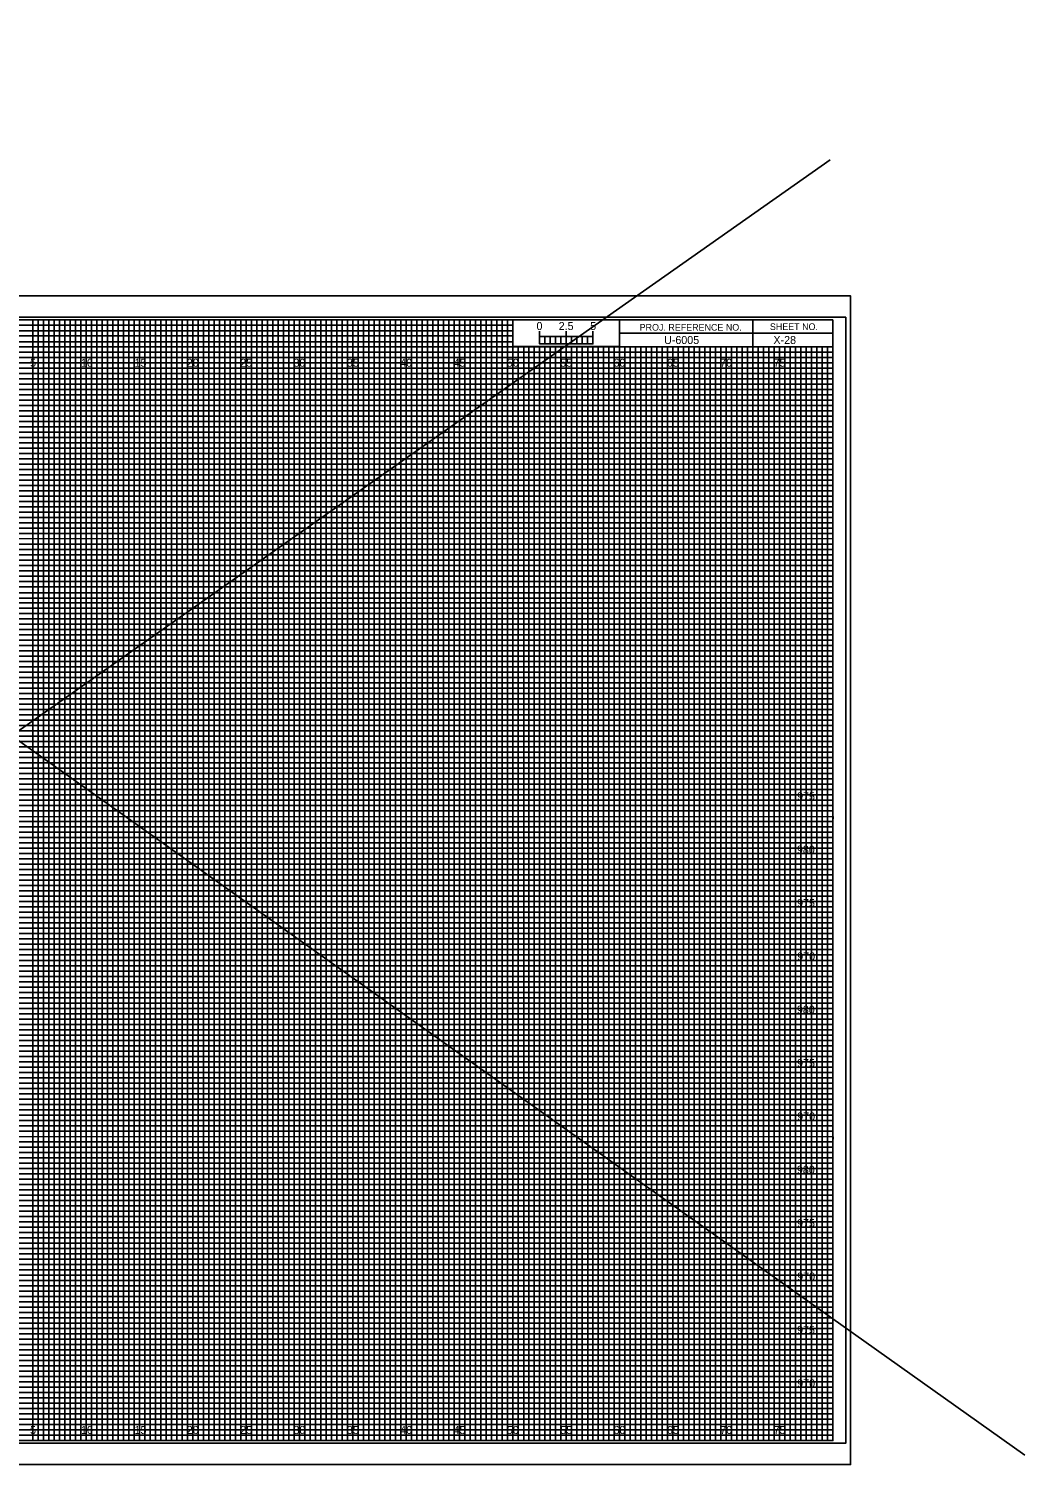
# Model space of a CAD drawing. Extents: x -16 to 178, y -4 to 132.
# Drawn here: x 84.6 to 178, y -3.6 to 132.3 of the extents above; entities that cross this region are included whole.
import ezdxf

# ---------------------------------------------------------------- set-up
doc = ezdxf.new("R2010")
doc.units = 0
for name, color, linetype in [('Default', 7, 'Continuous'), ('Exist Cross Section Cell', 7, 'Continuous'), ('Exist XS Center Line Elevation Label', 7, 'Continuous'), ('Exist XS Ground Line', 7, 'Continuous'), ('Prop XS Ditch Slope Text', 7, 'Continuous'), ('Prop XS Ditch Standard Text', 7, 'Continuous'), ('Prop XS Dump Level', 7, 'Continuous'), ('Prop XS EOT Tick Mark', 7, 'Continuous'), ('Prop XS Finish Grade', 7, 'Continuous'), ('Prop XS Finish Grade CurbGutter', 7, 'Continuous'), ('Prop XS Finish Grade Earthwork', 7, 'Continuous'), ('Prop XS Finish Grade Pavement', 7, 'Continuous'), ('Prop XS SE Text', 7, 'Continuous'), ('Prop XS Side Slope Text', 7, 'Continuous'), ('Prop XS SS Elevation Text', 7, 'Continuous'), ('Prop XS Subgrade Earthwork', 7, 'Continuous')]:
    doc.layers.add(name, color=color, linetype=linetype)

msp = doc.modelspace()

# ---------------------------------------------------------------- linework, layer by layer
at = {"layer": 'Default'}
for p, q in [((178, -1.35), (-10.3, 132.27)), ((-16.05, -3.6), (159.75, 120))]:
    msp.add_line(p, q, dxfattribs=at)
at = {"layer": 'Exist XS Center Line Elevation Label'}
for points in [[(82.5, 0), (87.5, 0), (87.5, 105), (92.5, 105), (92.5, 0), (97.5, 0), (97.5, 105), (102.5, 105), (102.5, 0), (107.5, 0), (107.5, 105), (112.5, 105), (112.5, 0), (117.5, 0), (117.5, 105), (122.5, 105), (122.5, 0), (127.5, 0), (127.5, 105), (129.97, 105), (130, 105), (130, 102.5), (132.5, 102.5), (132.5, 0), (137.5, 0), (137.5, 102.5), (142.5, 102.5), (142.5, 0), (147.5, 0), (147.5, 102.5), (152.5, 102.5), (152.5, 0), (157.5, 0), (157.5, 102.5)], [(0, 102.5), (137.5, 102.5)], [(0, 92.5), (160, 92.5), (160, 97.5), (0, 97.5)], [(0, 82.5), (160, 82.5), (160, 87.5), (0, 87.5)], [(0, 72.5), (160, 72.5), (160, 77.5), (0, 77.5)], [(0, 62.5), (160, 62.5), (160, 67.5), (0, 67.5)], [(0, 52.5), (160, 52.5), (160, 57.5), (0, 57.5)], [(0, 42.5), (160, 42.5), (160, 47.5), (0, 47.5)], [(0, 32.5), (160, 32.5), (160, 37.5), (0, 37.5)], [(0, 22.5), (160, 22.5), (160, 27.5), (0, 27.5)], [(0, 12.5), (160, 12.5), (160, 17.5), (0, 17.5)], [(0, 2.5), (160, 2.5), (160, 7.5), (0, 7.5)]]:
    msp.add_lwpolyline(points, dxfattribs=at)
at = {"layer": 'Exist XS Ground Line'}
for p, q in [((85, 105), (80, 105)), ((85, 0), (85, 105)), ((95, 105), (90, 105)), ((90, 105), (90, 0)), ((95, 0), (95, 105)), ((105, 105), (100, 105)), ((100, 105), (100, 0)), ((105, 0), (105, 105)), ((115, 105), (110, 105)), ((110, 105), (110, 0)), ((115, 0), (115, 105)), ((125, 105), (120, 105)), ((120, 105), (120, 0)), ((125, 0), (125, 105)), ((130, 105), (130, 0)), ((135, 0), (135, 102.5)), ((145, 102.5), (140, 102.5)), ((140, 102.5), (140, 0)), ((145, 0), (145, 102.5)), ((155, 102.5), (150, 102.5)), ((150, 102.5), (150, 0)), ((155, 0), (155, 102.5)), ((90, 0), (85, 0)), ((100, 0), (95, 0)), ((110, 0), (105, 0)), ((120, 0), (115, 0)), ((130, 0), (125, 0)), ((140, 0), (135, 0)), ((150, 0), (145, 0)), ((160, 0), (155, 0)), ((160, 0), (160, 0))]:
    msp.add_line(p, q, dxfattribs=at)
for points in [[(0, 100), (160, 100), (160, 95), (0, 95)], [(0, 90), (160, 90), (160, 85), (0, 85)], [(0, 80), (160, 80), (160, 75), (0, 75)], [(0, 70), (160, 70), (160, 65), (0, 65)], [(0, 60), (160, 60), (160, 55), (0, 55)], [(0, 50), (160, 50), (160, 45), (0, 45)], [(0, 40), (160, 40), (160, 35), (0, 35)], [(0, 30), (160, 30), (160, 25), (0, 25)], [(0, 20), (160, 20), (160, 15), (0, 15)], [(0, 10), (160, 10), (160, 5), (0, 5)]]:
    msp.add_lwpolyline(points, dxfattribs=at)
at = {"layer": 'Prop XS Ditch Slope Text'}
for p, q in [((132.5, 102.75), (132.5, 103.95)), ((132.5, 103.45), (132.5, 103.95)), ((135, 102.75), (135, 103.95)), ((137.5, 102.75), (137.5, 103.95)), ((137.5, 103.45), (137.5, 103.95))]:
    msp.add_line(p, q, dxfattribs=at)
for points in [[(137.5, 103.45), (132.5, 103.45), (132.5, 102.75), (137.5, 102.75)], [(132.5, 103.45), (133, 103.45), (133, 102.75), (132.5, 102.75)], [(133.5, 103.45), (134, 103.45), (134, 102.75), (133.5, 102.75)], [(134.5, 103.45), (135, 103.45), (135, 102.75), (134.5, 102.75)], [(135.5, 103.45), (136, 103.45), (136, 102.75), (135.5, 102.75)], [(136.5, 103.45), (137, 103.45), (137, 102.75), (136.5, 102.75)]]:
    msp.add_lwpolyline(points, close=True, dxfattribs=at)
at = {"layer": 'Prop XS Ditch Standard Text'}
for p, q in [((133.5, 102.5), (133, 102.5)), ((133, 102.5), (133, 0)), ((133.5, 0), (133.5, 102.5)), ((134.5, 102.5), (134, 102.5)), ((134, 102.5), (134, 0)), ((134.5, 0), (134.5, 102.5)), ((133, 0), (132.5, 0)), ((134, 0), (133.5, 0))]:
    msp.add_line(p, q, dxfattribs=at)
for points in [[(85, 0), (85.5, 0), (85.5, 105), (86, 105), (86, 0)], [(86, 0), (86.5, 0), (86.5, 105), (87, 105), (87, 0)], [(87.5, 0), (88, 0), (88, 105), (88.5, 105), (88.5, 0)], [(88.5, 0), (89, 0), (89, 105), (89.5, 105), (89.5, 0)], [(90, 0), (90.5, 0), (90.5, 105), (91, 105), (91, 0)], [(91, 0), (91.5, 0), (91.5, 105), (92, 105), (92, 0)], [(92.5, 0), (93, 0), (93, 105), (93.5, 105), (93.5, 0)], [(93.5, 0), (94, 0), (94, 105), (94.5, 105), (94.5, 0)], [(95, 0), (95.5, 0), (95.5, 105), (96, 105), (96, 0)], [(96, 0), (96.5, 0), (96.5, 105), (97, 105), (97, 0)], [(97.5, 0), (98, 0), (98, 105), (98.5, 105), (98.5, 0)], [(98.5, 0), (99, 0), (99, 105), (99.5, 105), (99.5, 0)], [(100, 0), (100.5, 0), (100.5, 105), (101, 105), (101, 0)], [(101, 0), (101.5, 0), (101.5, 105), (102, 105), (102, 0)], [(102.5, 0), (103, 0), (103, 105), (103.5, 105), (103.5, 0)], [(103.5, 0), (104, 0), (104, 105), (104.5, 105), (104.5, 0)], [(105, 0), (105.5, 0), (105.5, 105), (106, 105), (106, 0)], [(106, 0), (106.5, 0), (106.5, 105), (107, 105), (107, 0)], [(107.5, 0), (108, 0), (108, 105), (108.5, 105), (108.5, 0)], [(108.5, 0), (109, 0), (109, 105), (109.5, 105), (109.5, 0)], [(110, 0), (110.5, 0), (110.5, 105), (111, 105), (111, 0)], [(111, 0), (111.5, 0), (111.5, 105), (112, 105), (112, 0)], [(112.5, 0), (113, 0), (113, 105), (113.5, 105), (113.5, 0)], [(113.5, 0), (114, 0), (114, 105), (114.5, 105), (114.5, 0)], [(115, 0), (115.5, 0), (115.5, 105), (116, 105), (116, 0)], [(116, 0), (116.5, 0), (116.5, 105), (117, 105), (117, 0)], [(117.5, 0), (118, 0), (118, 105), (118.5, 105), (118.5, 0)], [(118.5, 0), (119, 0), (119, 105), (119.5, 105), (119.5, 0)], [(120, 0), (120.5, 0), (120.5, 105), (121, 105), (121, 0)], [(121, 0), (121.5, 0), (121.5, 105), (122, 105), (122, 0)], [(122.5, 0), (123, 0), (123, 105), (123.5, 105), (123.5, 0)], [(123.5, 0), (124, 0), (124, 105), (124.5, 105), (124.5, 0)], [(125, 0), (125.5, 0), (125.5, 105), (126, 105), (126, 0)], [(126, 0), (126.5, 0), (126.5, 105), (127, 105), (127, 0)], [(127.5, 0), (128, 0), (128, 105), (128.5, 105), (128.5, 0)], [(128.5, 0), (129, 0), (129, 105), (129.5, 105), (129.5, 0)], [(130, 0), (130.5, 0), (130.5, 102.5), (131.01, 102.5), (131.01, 0)], [(131, 0), (131.5, 0), (131.5, 102.5), (132, 102.5), (132, 0)], [(135, 0), (135.49, 0), (135.49, 102.5), (136, 102.5), (136, 0)], [(136, 0), (136.5, 0), (136.5, 102.5), (137.03, 102.5), (137.03, 0)], [(137.5, 0), (138, 0), (138, 102.5), (138.5, 102.5), (138.5, 0)], [(138.5, 0), (139, 0), (139, 102.5), (139.5, 102.5), (139.5, 0)], [(140, 0), (140.5, 0), (140.5, 102.5), (141, 102.5), (141, 0)], [(141, 0), (141.5, 0), (141.5, 102.5), (142, 102.5), (142, 0)], [(142.5, 0), (143, 0), (143, 102.5), (143.5, 102.5), (143.5, 0)], [(143.5, 0), (144, 0), (144, 102.5), (144.5, 102.5), (144.5, 0)], [(145, 0), (145.5, 0), (145.5, 102.5), (146, 102.5), (146, 0)], [(146, 0), (146.5, 0), (146.5, 102.5), (147, 102.5), (147, 0)], [(147.5, 0), (148, 0), (148, 102.5), (148.5, 102.5), (148.5, 0)], [(148.5, 0), (149, 0), (149, 102.5), (149.5, 102.5), (149.5, 0)], [(150, 0), (150.5, 0), (150.5, 102.5), (151, 102.5), (151, 0)], [(151, 0), (151.5, 0), (151.5, 102.5), (152, 102.5), (152, 0)], [(152.5, 0), (153, 0), (153, 102.5), (153.5, 102.5), (153.5, 0)], [(153.5, 0), (154, 0), (154, 102.5), (154.5, 102.5), (154.5, 0)], [(155, 0), (155.5, 0), (155.5, 102.5), (156, 102.5), (156, 0)], [(156, 0), (156.5, 0), (156.5, 102.5), (157, 102.5), (157, 0)], [(157.5, 0), (158, 0), (158, 102.5), (158.5, 102.5), (158.5, 0)], [(158.5, 0), (159, 0), (159, 102.5), (159.5, 102.5), (159.5, 0)]]:
    msp.add_lwpolyline(points, dxfattribs=at)
at = {"layer": 'Prop XS Dump Level'}
for p, q in [((0, 104.5), (130, 104.5)), ((130, 103.99), (0, 103.99)), ((0, 103.5), (130, 103.5)), ((130, 104.5), (130, 103.99)), ((130, 103.5), (130, 102.95)), ((130, 102.95), (0, 102.95)), ((0, 102), (160, 102))]:
    msp.add_line(p, q, dxfattribs=at)
for points in [[(0, 101.5), (135, 101.5), (160, 101.5), (160, 101), (0, 101)], [(0, 100.5), (160, 100.5), (160, 99.5), (0, 99.5)], [(0, 99), (160, 99), (160, 98.5), (0, 98.49)], [(0, 98), (160, 98), (160, 97), (0, 97)], [(0, 96.5), (160, 96.5), (160, 96), (0, 96)], [(0, 95.5), (160, 95.5), (160, 94.5), (0, 94.5)], [(0, 94), (160, 94), (160, 93.5), (0, 93.5)], [(0, 93), (160, 93), (160, 92), (0, 92)], [(0, 91.5), (160, 91.5), (160, 91), (0, 91)], [(0, 90.5), (160, 90.5), (160, 89.5), (0, 89.5)], [(0, 89), (160, 89), (160, 88.5), (0, 88.5)], [(0, 88), (160, 88), (160, 86.98), (160, 86.5), (160, 86), (0, 86)], [(0, 87), (160, 87), (160, 86.5), (0, 86.5)], [(0, 85.5), (160, 85.5), (160, 84.5), (0, 84.52)], [(0, 84.52), (160, 84.5), (160, 84), (0, 84)], [(0, 83.5), (160, 83.5), (160, 83), (0, 83)], [(0, 82), (160, 82), (160, 81.5), (0, 81.5)], [(0, 81), (160, 81), (160, 80.5), (0, 80.5)], [(-0.04, 79.45), (160, 79.45), (160, 78.94), (-0.04, 78.94)], [(0, 78.5), (160, 78.5), (160, 78), (0, 78)], [(0, 77), (160, 77), (160, 76.5), (0, 76.5)], [(0, 76), (160, 76), (160, 75.5), (0, 75.5)], [(0, 74.5), (160, 74.5), (160, 74), (0, 74)], [(0, 73.5), (160, 73.5), (160, 73), (0, 73)], [(0, 72), (160, 72), (160, 71.5), (0, 71.5)], [(0, 71), (160, 71), (160, 70.5), (0, 70.5)], [(0, 69.5), (160, 69.5), (160, 68.99), (0, 69)], [(0, 68.5), (160, 68.5), (160, 68), (0, 68)], [(0, 67), (160, 67), (160, 66.5), (0, 66.5)], [(0, 66), (160, 66), (160, 65.5), (0, 65.5)], [(0, 64.5), (160, 64.5), (160, 64), (0, 64)], [(0, 63.5), (160, 63.5), (160, 63), (0, 63)], [(0, 62), (160, 62), (160, 61.5), (0, 61.5)], [(0, 61), (160, 61), (160, 60.5), (0, 60.5)], [(0, 59.5), (160, 59.5), (160, 59), (0, 59)], [(0, 58.5), (160.03, 58.45), (160, 58), (0, 58)], [(0, 57), (160, 57), (160, 56.5), (0, 56.5)], [(0, 56), (160, 56), (160, 55.5), (0, 55.5)], [(0, 54.5), (160, 54.5), (160, 54), (0, 54)], [(0, 53.5), (160, 53.5), (160, 53), (0, 53)], [(0, 52), (160, 52), (160, 51.5), (0, 51.5)], [(0, 51), (160, 51), (160, 50.5), (0, 50.5)], [(0, 49.5), (160, 49.5), (160, 49), (0, 49)], [(0, 48.5), (160, 48.5), (160, 48), (0, 48)], [(0, 47), (160, 47), (160, 46.5), (0, 46.5)], [(0, 46), (160, 46), (160, 45.5), (0, 45.5)], [(0, 44.5), (160, 44.5), (160, 44), (0, 44)], [(0, 43.5), (160, 43.5), (160, 43), (0, 43)], [(0, 42), (160, 42), (160, 41.5), (0, 41.5)], [(0, 41), (160, 41), (160, 40.5), (0, 40.5)], [(0, 39.5), (160, 39.5), (160, 38.99), (0, 39)], [(0, 38.5), (160, 38.5), (160, 38), (0, 38)], [(0, 37), (160, 37), (160, 36.5), (0, 36.5)], [(0, 36), (160, 36), (160, 35.5), (0, 35.5)], [(0, 34.5), (160, 34.5), (160, 34), (0, 34)], [(0, 33.5), (160, 33.5), (160, 33), (0, 33)], [(0, 32), (160, 32), (160, 31.5), (0, 31.5)], [(0, 31), (160, 31), (160, 30.5), (0, 30.5)], [(0, 29.5), (160, 29.5), (160, 29), (0, 29)], [(0, 28.5), (160.03, 28.46), (160, 28), (0, 28)], [(0, 27), (160, 27), (160, 26.5), (0, 26.5)], [(0, 26), (160, 26), (160, 25.5), (0, 25.5)], [(0, 24.5), (160, 24.5), (160, 24), (0, 24)], [(0, 23.5), (160, 23.5), (160, 23), (0, 23)], [(0, 22), (160, 22), (160, 21.5), (0, 21.5)], [(0, 21), (160, 21), (160, 20.5), (0, 20.5)], [(0, 19.5), (160, 19.5), (160, 19), (0, 19)], [(0, 18.5), (160, 18.5), (160, 18), (0, 18)], [(0, 17), (160, 17), (160, 16.5), (0, 16.5)], [(0, 16), (160, 16), (160, 15.5), (0, 15.5)], [(0, 14.5), (160, 14.5), (160, 14), (0, 14)], [(0, 13.5), (160, 13.5), (160, 13), (0, 13)], [(0, 12), (160, 12), (160, 11.5), (0, 11.5)], [(0, 11), (160, 11), (160, 10.5), (0, 10.5)], [(0, 9.5), (160, 9.5), (160, 9), (0, 9)], [(0, 8.5), (160, 8.5), (160, 8), (0, 8)], [(0, 7), (160, 7), (160, 6.5), (0, 6.5)], [(0, 6), (160, 6), (160, 5.5), (0, 5.5)], [(0, 4.5), (160, 4.5), (160, 4), (0, 4)], [(0, 3.5), (160, 3.5), (160, 3), (0, 3)], [(0, 2), (160, 2), (160, 1.5), (0, 1.5)], [(0, 1), (160, 1), (160, 0.5), (0, 0.5)]]:
    msp.add_lwpolyline(points, dxfattribs=at)
at = {"layer": 'Prop XS Finish Grade Earthwork'}
for p, q in [((85, 0), (85, 105)), ((90, 0), (90, 105)), ((95, 0), (95, 105)), ((100, 0), (100, 105)), ((105, 0), (105, 105)), ((110, 0), (110, 105)), ((115, 0), (115, 105)), ((120, 0), (120, 105)), ((125, 0), (125, 105)), ((130, 0), (130, 102.34)), ((135, 0), (135, 102.34)), ((140, 0), (140, 102.34)), ((145, 0), (145, 102.34)), ((150, 0), (150, 102.34)), ((155, 0), (155, 102.34)), ((0, 100), (160, 100)), ((0, 95), (160, 95)), ((0, 90), (160, 90)), ((0, 85), (160, 85)), ((0, 80), (160, 80)), ((0, 75), (160, 75)), ((0, 70), (160, 70)), ((0, 65), (160, 65)), ((0, 60), (160, 60)), ((0, 55), (160, 55)), ((0, 50), (160, 50)), ((0, 45), (160, 45)), ((0, 40), (160, 40)), ((0, 35), (160, 35)), ((0, 30), (160, 30)), ((0, 25), (160, 25)), ((0, 20), (160, 20)), ((0, 15), (160, 15)), ((0, 10), (160, 10)), ((0, 5), (160, 5))]:
    msp.add_line(p, q, dxfattribs=at)
at = {"layer": 'Prop XS SE Text'}
for p, q in [((152.5, 105), (152.5, 102.5)), ((152.5, 102.5), (152.5, 105)), ((160, 103.75), (140, 103.75)), ((140, 103.75), (140, 102.5)), ((140, 102.5), (160, 102.5))]:
    msp.add_line(p, q, dxfattribs=at)
for points in [[(160, 105), (0, 105), (0, 0), (160, 0)], [(140, 105), (130, 105), (130, 102.52), (140, 102.52)], [(160, 105), (140, 105), (140, 102.5), (160, 102.5)]]:
    msp.add_lwpolyline(points, close=True, dxfattribs=at)
at = {"layer": 'Prop XS Side Slope Text'}
msp.add_lwpolyline([(-6.7, -2.25), (161.65, -2.25), (161.65, 107.25), (-6.7, 107.25)], close=True, dxfattribs=at)
at = {"layer": 'Prop XS SS Elevation Text'}
msp.add_lwpolyline([(-5.4, -0.25), (161.2, -0.25), (161.2, 105.25), (-5.4, 105.25)], close=True, dxfattribs=at)
at = {"layer": 'Prop XS Subgrade Earthwork'}
for p, q in [((161.65, 107.25), (-6.7, 107.25)), ((-6.7, -2.25), (161.65, -2.25))]:
    msp.add_line(p, q, dxfattribs=at)

# ---------------------------------------------------------------- texts
at = {"layer": 'Exist Cross Section Cell'}
for s, p in [('5', (84.74, 100.62)), ('10', (89.52, 100.62)), ('15', (94.53, 100.62)), ('20', (99.43, 100.62)), ('25', (104.44, 100.62)), ('30', (109.43, 100.62)), ('35', (114.44, 100.62)), ('40', (119.43, 100.62)), ('45', (124.44, 100.62)), ('50', (129.43, 100.62)), ('55', (134.44, 100.62)), ('60', (139.43, 100.62)), ('65', (144.44, 100.62)), ('70', (149.43, 100.62)), ('75', (154.44, 100.62)), ('5', (84.74, 0.62)), ('10', (89.52, 0.62)), ('15', (94.53, 0.62)), ('20', (99.43, 0.62)), ('25', (104.44, 0.62)), ('30', (109.43, 0.62)), ('35', (114.44, 0.62)), ('40', (119.43, 0.62)), ('45', (124.44, 0.62)), ('50', (129.43, 0.62)), ('55', (134.44, 0.62)), ('60', (139.43, 0.62)), ('65', (144.44, 0.62)), ('70', (149.43, 0.62)), ('75', (154.44, 0.62))]:
    msp.add_text(s, height=0.75, dxfattribs=at).set_placement(p)
at = {"layer": 'Prop XS Ditch Slope Text'}
msp.add_text('0', height=0.75, dxfattribs=at).set_placement((132.21, 104.06))
at = {"layer": 'Prop XS EOT Tick Mark'}
msp.add_text('X-28', height=0.75, dxfattribs=at).set_placement((154.42, 102.75))
at = {"layer": 'Prop XS Finish Grade'}
for s, p in [('975', (156.64, 60)), ('980', (156.62, 55)), ('975', (156.64, 50)), ('970', (156.65, 45)), ('980', (156.62, 40)), ('975', (156.64, 35)), ('970', (156.65, 30)), ('980', (156.62, 25)), ('975', (156.64, 20)), ('970', (156.65, 15)), ('975', (156.64, 10)), ('970', (156.65, 5))]:
    msp.add_text(s, height=0.75, dxfattribs=at).set_placement(p)
at = {"layer": 'Prop XS Finish Grade CurbGutter'}
for s, p in [('2.5', (134.29, 104.06)), ('5', (137.24, 104.06))]:
    msp.add_text(s, height=0.75, dxfattribs=at).set_placement(p)
at = {"layer": 'Prop XS Finish Grade Pavement'}
msp.add_text('U-6005', height=0.75, dxfattribs=at).set_placement((144.17, 102.75))
at = {"layer": 'Prop XS SE Text'}
for s, p in [('PROJ. REFERENCE NO.', (141.88, 104)), ('SHEET NO.', (154.09, 104.06))]:
    msp.add_text(s, height=0.625, dxfattribs=at).set_placement(p)

doc.saveas('drawing.dxf')
